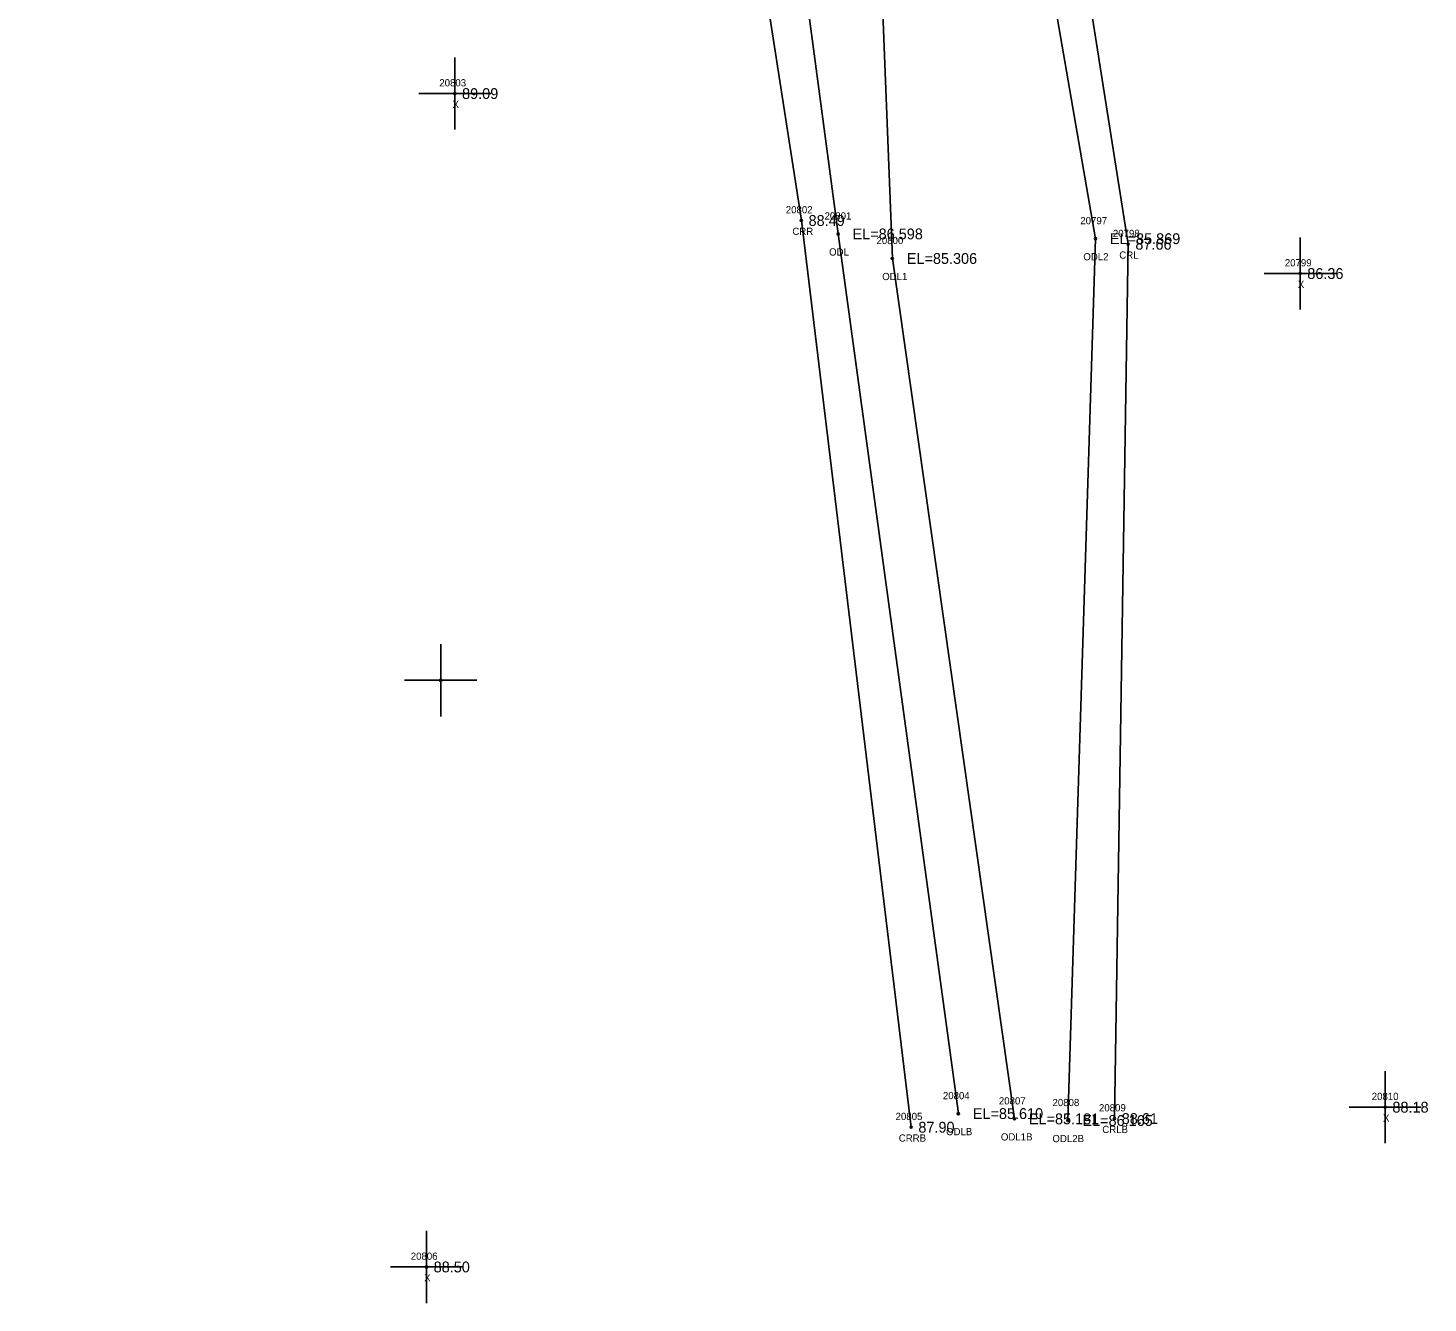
# Model space of a CAD drawing. Extents: x 2530197 to 2532051, y 935230 to 936631.
# Drawn here: x 2531078.9 to 2531273.1, y 935422.3 to 935599.2 of the extents above; entities that cross this region are included whole.
import ezdxf

# ---------------------------------------------------------------- set-up
doc = ezdxf.new("R2010")
doc.units = 0
for name, color, linetype in [('RD_EX_H2O', 7, 'Continuous'), ('RD_EX_H2O_txCode', 7, 'Continuous'), ('RD_EX_Misc', 7, 'Continuous'), ('RD_EX_Misc_txCode', 7, 'Continuous'), ('RD_EX_TX_H2O_ELEV', 7, 'Continuous'), ('RD_EX_TX_Misc_ELEV', 7, 'Continuous'), ('RD_SMD_Locator', 7, 'Continuous')]:
    doc.layers.add(name, color=color, linetype=linetype)

msp = doc.modelspace()

# ---------------------------------------------------------------- linework, layer by layer
at = {"layer": 'RD_EX_H2O'}
for points in [[(2531169.61, 936003.09), (2531168.21, 936006.21), (2531167.04, 936004.54), (2531167.21, 936003.45), (2531176, 935975.44), (2531176.84, 935974.76), (2531177.07, 935973.85), (2531179, 935967.11), (2531180.39, 935948.02), (2531175.92, 935941.33), (2531173.5, 935933.2), (2531181.71, 935892.9), (2531201.16, 935775.97), (2531215.24, 935672.42), (2531231.54, 935569.22), (2531229.65, 935447.9)], [(2531151.41, 935999.3), (2531160.42, 935966.87), (2531174.33, 935892.02), (2531192.74, 935775.85), (2531209.3, 935672.4), (2531227.01, 935569.99), (2531223.19, 935447.63)], [(2531123.96, 935982.91), (2531138.41, 935953.66), (2531150.01, 935894.11), (2531170.89, 935766.15), (2531194.87, 935668.24), (2531198.82, 935567.24), (2531215.76, 935447.86)], [(2531095.07, 935962.75), (2531122.05, 935944.01), (2531139.42, 935896.32), (2531161, 935756.43), (2531179.99, 935655.36), (2531191.29, 935570.65), (2531207.98, 935448.59)], [(2531078.88, 935952.28), (2531078.96, 935951.18), (2531094.18, 935926.97), (2531103.29, 935929.49), (2531106.67, 935929.67), (2531109.75, 935927.85), (2531109.94, 935928.67), (2531111.53, 935928.19), (2531109.98, 935924.15), (2531114.47, 935921.71), (2531121.2, 935920.45), (2531134.65, 935891.6), (2531155.43, 935754.46), (2531173.73, 935652.91), (2531186.19, 935572.51), (2531201.43, 935446.7)]]:
    msp.add_lwpolyline(points, dxfattribs=at)
at = {"layer": 'RD_EX_Misc'}
for p, q in [((2531138.11, 935585.12), (2531138.11, 935595.12)), ((2531133.11, 935590.12), (2531143.11, 935590.12)), ((2531255.4, 935560.15), (2531255.4, 935570.15)), ((2531250.4, 935565.15), (2531260.4, 935565.15)), ((2531136.14, 935503.71), (2531136.14, 935513.71)), ((2531131.14, 935508.71), (2531141.14, 935508.71)), ((2531267.21, 935444.48), (2531267.21, 935454.48)), ((2531262.21, 935449.48), (2531272.21, 935449.48)), ((2531134.17, 935422.31), (2531134.17, 935432.31)), ((2531129.17, 935427.31), (2531139.17, 935427.31))]:
    msp.add_line(p, q, dxfattribs=at)
at = {"layer": 'RD_SMD_Locator'}
for centre in [(2531138.11, 935590.12), (2531186.19, 935572.51), (2531191.29, 935570.65), (2531227.01, 935569.99), (2531231.54, 935569.22), (2531198.82, 935567.24), (2531255.4, 935565.15), (2531136.14, 935508.71), (2531267.21, 935449.48), (2531207.98, 935448.59), (2531215.76, 935447.86), (2531223.19, 935447.63), (2531229.65, 935447.9), (2531201.43, 935446.7), (2531134.17, 935427.31)]:
    msp.add_circle(centre, 0.15, dxfattribs=at)

# ---------------------------------------------------------------- texts
at = {"layer": 'RD_EX_H2O_txCode'}
for s, p in [('20802', (2531184.03, 935573.51)), ('20801', (2531189.41, 935572.65)), ('20797', (2531224.9, 935571.99)), ('CRR', (2531184.94, 935570.51)), ('20800', (2531196.62, 935569.24)), ('20798', (2531229.42, 935570.22)), ('ODL', (2531190.04, 935567.65)), ('CRL', (2531230.31, 935567.22)), ('ODL2', (2531225.32, 935566.99)), ('ODL1', (2531197.41, 935564.24)), ('20804', (2531205.83, 935450.59)), ('20807', (2531213.6, 935449.86)), ('20808', (2531221.04, 935449.63)), ('20809', (2531227.49, 935448.9)), ('20805', (2531199.27, 935447.7)), ('CRRB', (2531199.71, 935444.7)), ('ODLB', (2531206.27, 935445.59)), ('ODL1B', (2531213.88, 935444.86)), ('CRLB', (2531227.95, 935445.9)), ('ODL2B', (2531221.03, 935444.63))]:
    msp.add_text(s, height=1, dxfattribs=at).set_placement(p)
at = {"layer": 'RD_EX_Misc_txCode'}
for s, p in [('20803', (2531135.95, 935591.12)), ('X', (2531137.79, 935588.12)), ('20799', (2531253.28, 935566.15)), ('X', (2531255.08, 935563.15)), ('20810', (2531265.34, 935450.48)), ('X', (2531266.9, 935447.48)), ('20806', (2531131.99, 935428.31)), ('X', (2531133.85, 935425.31))]:
    msp.add_text(s, height=1, dxfattribs=at).set_placement(p)
at = {"layer": 'RD_EX_TX_H2O_ELEV'}
for s, p in [('88.49', (2531187.19, 935571.76)), ('EL=86.598', (2531193.29, 935569.9)), ('EL=85.869', (2531229.01, 935569.24)), ('87.66', (2531232.54, 935568.47)), ('EL=85.306', (2531200.82, 935566.49)), ('EL=85.610', (2531209.98, 935447.84)), ('EL=85.181', (2531217.76, 935447.11)), ('EL=86.165', (2531225.19, 935446.88)), ('88.61', (2531230.65, 935447.15)), ('87.90', (2531202.43, 935445.95))]:
    msp.add_text(s, height=1.5, dxfattribs=at).set_placement(p)
at = {"layer": 'RD_EX_TX_Misc_ELEV'}
for s, p in [('89.09', (2531139.11, 935589.37)), ('86.36', (2531256.4, 935564.4)), ('88.18', (2531268.21, 935448.73)), ('88.50', (2531135.17, 935426.56))]:
    msp.add_text(s, height=1.5, dxfattribs=at).set_placement(p)

doc.saveas('drawing.dxf')
